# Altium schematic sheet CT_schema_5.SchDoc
size 368 x 245 mm
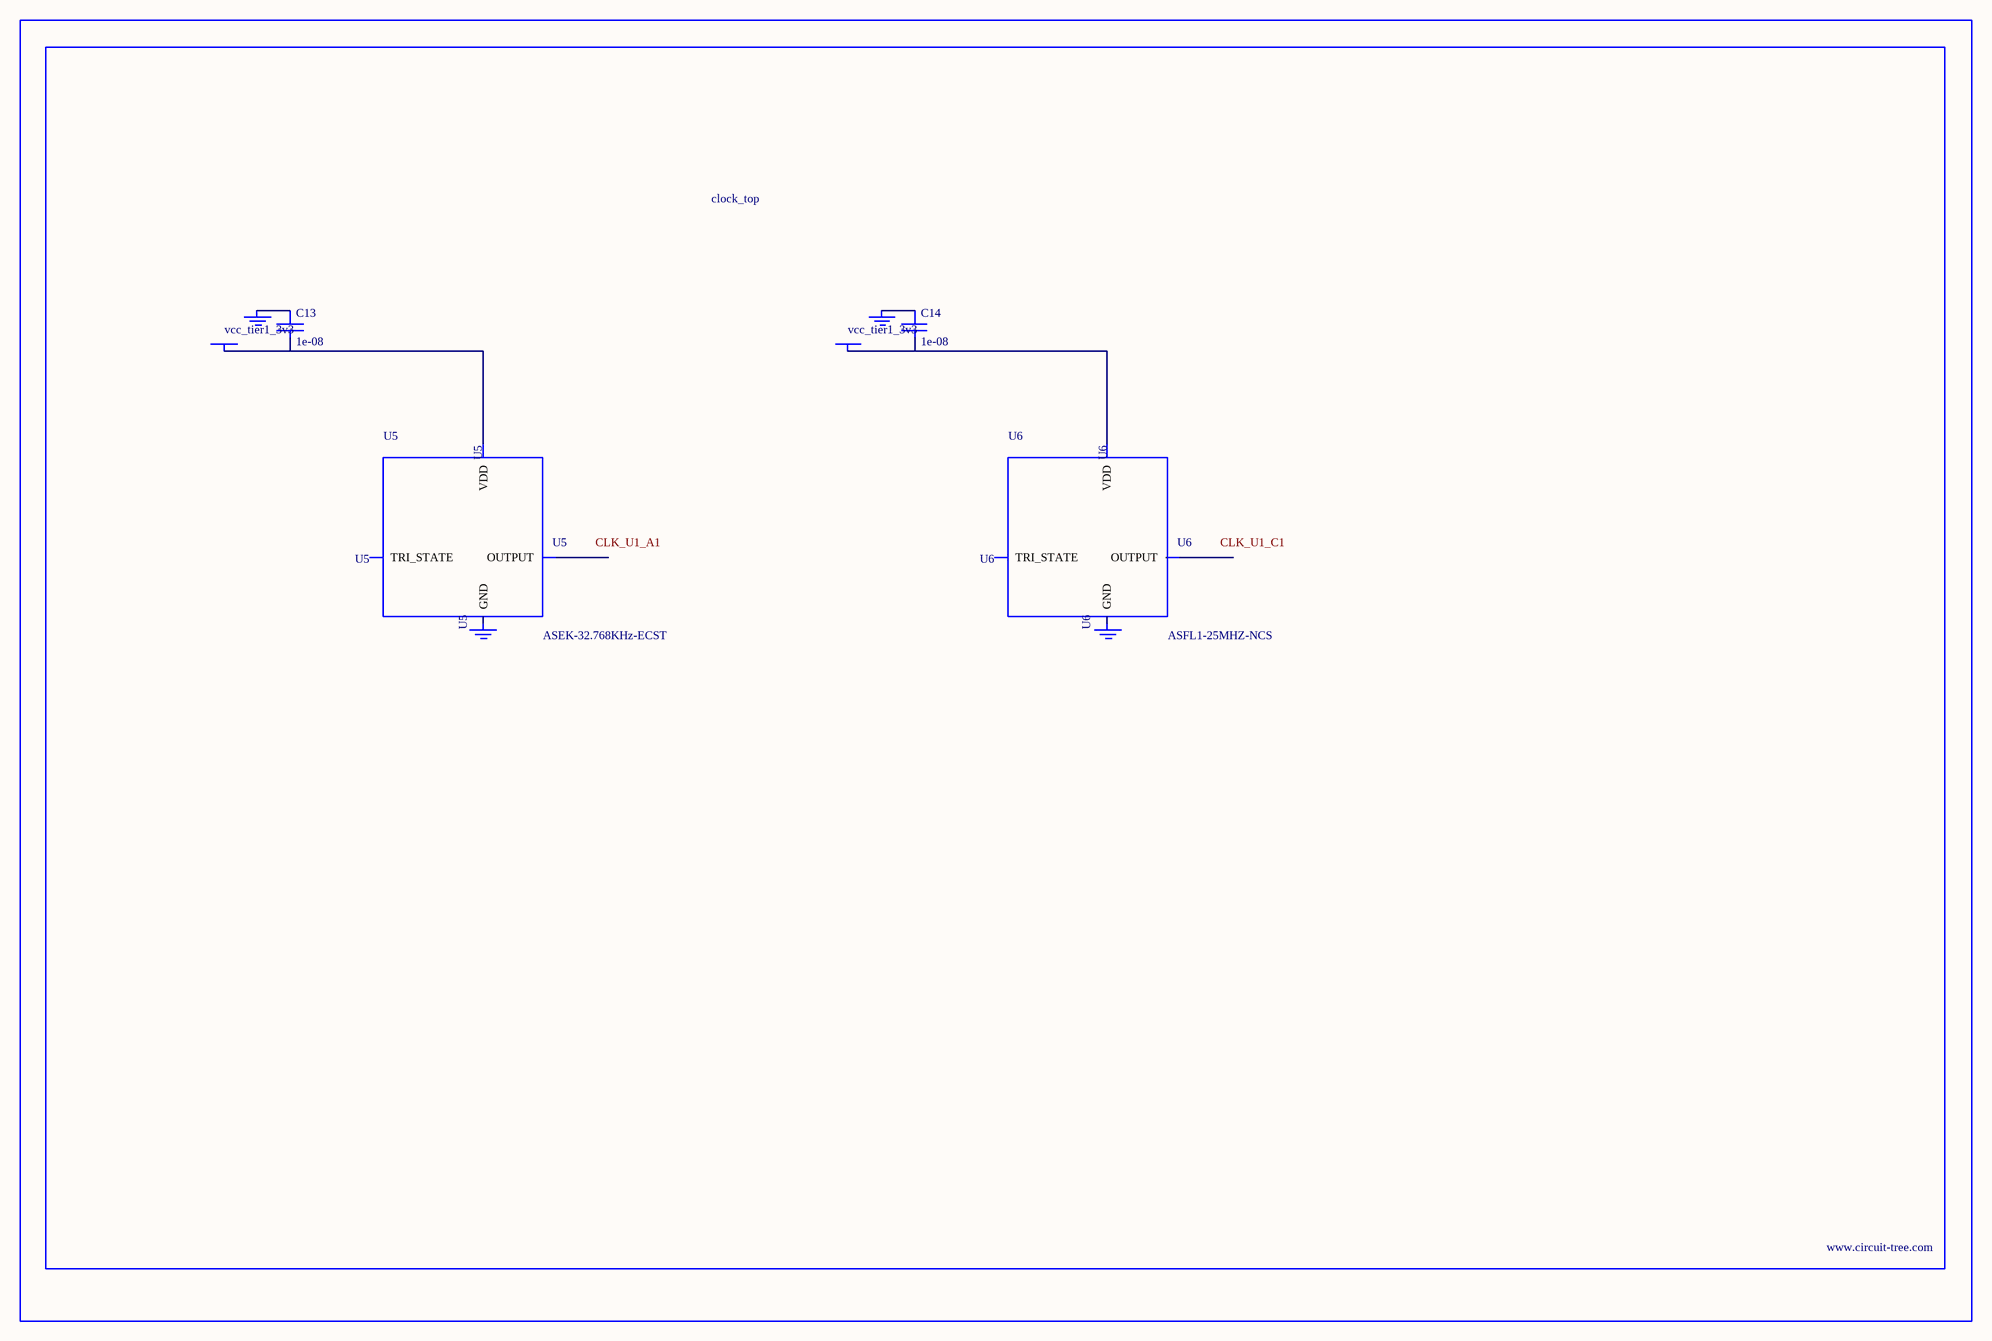
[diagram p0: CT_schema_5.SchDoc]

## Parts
BORDER4  (no value)
C13  1e-08  [C0402]
C14  1e-08  [C0402]
GND_INSTANCE_4_0  (no value)
GND_INSTANCE_4_1  (no value)
GND_INSTANCE_4_2  (no value)
GND_INSTANCE_4_3  (no value)
POWER_INSTANCE_4_0  vcc_tier1_3v3
POWER_INSTANCE_4_1  vcc_tier1_3v3
U5  ASEK-32.768KHz-ECST  [ASEK]
U6  ASFL1-25MHZ-NCS  [ASFL1]

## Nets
NetC13_1: C13.1 GND_INSTANCE_4_0.0(GND)
NetC13_2: C13.2 POWER_INSTANCE_4_0.0(PWR) U5.4(VDD)
NetC14_1: C14.1 GND_INSTANCE_4_2.0(GND)
NetC14_2: C14.2 POWER_INSTANCE_4_1.0(PWR) U6.4(VDD)

Not connected (* = marked no-connect by the designer): GND_INSTANCE_4_1 0(GND); GND_INSTANCE_4_3 0(GND); U5 1(TRI_STATE) 2(GND) 3(OUTPUT); U6 1(TRI_STATE) 2(GND) 3(OUTPUT)

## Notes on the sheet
- Labels drawn without touching a wire or pin: CLK_U1_A1, CLK_U1_C1

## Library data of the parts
BORDER4 = BORDER_PAGE4
C13 C14 = C0402C103K3RAC
GND_INSTANCE_4_0-GND_INSTANCE_4_3 = GND
POWER_INSTANCE_4_0 POWER_INSTANCE_4_1 = PWR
